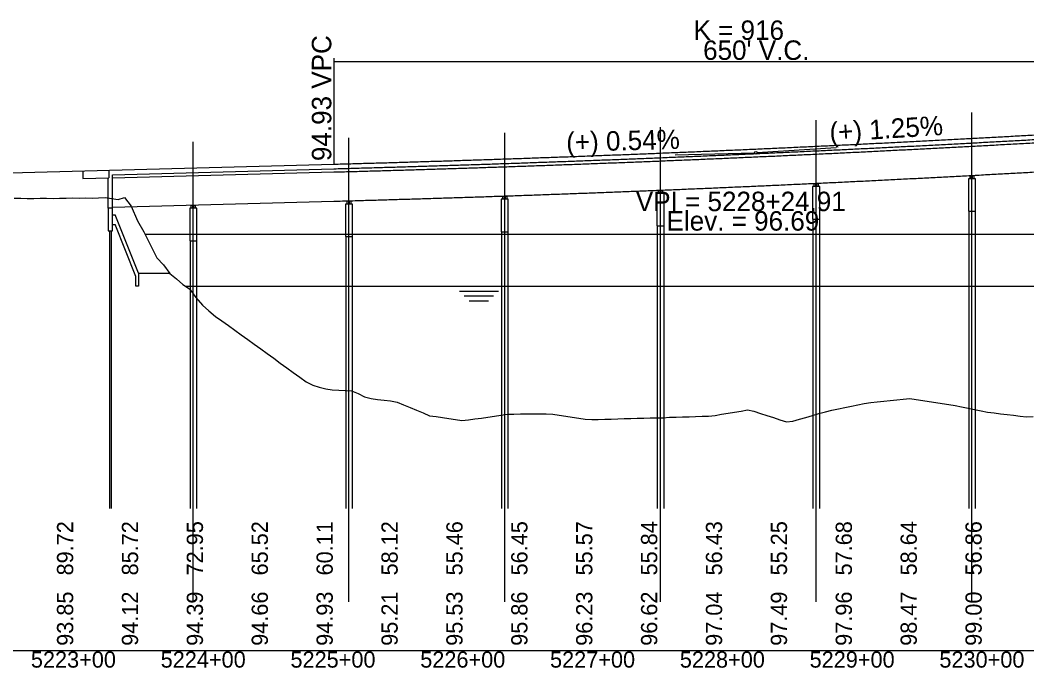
# Model space of a CAD drawing. Extents: x 2121671 to 2169879, y 557274 to 599957.
# Drawn here: x 2151826 to 2152602, y 579173 to 579672 of the extents above; entities that cross this region are included whole.
import ezdxf

# ---------------------------------------------------------------- set-up
doc = ezdxf.new("R2010")
doc.units = 0
for name, color, linetype in [('BR_CENTER LINES', 7, 'Continuous'), ('BR_CONCRETE', 7, 'Continuous'), ('BR_DETAILS', 7, 'Continuous'), ('BR_PRESTRESSED BEAM', 7, 'Continuous'), ('BR_STRUCTURAL STEEL', 7, 'Continuous'), ('RD_DDB_GradeTX', 7, 'Continuous'), ('RD_DDB_Profile_Elev', 7, 'Continuous'), ('RD_DDB_Profile_EX', 7, 'Continuous'), ('RD_DDB_Profile_Lbl', 7, 'Continuous'), ('RD_DDB_Profile_PR', 7, 'Continuous'), ('RD_DDB_StaTX', 7, 'Continuous'), ('RD_DDB_StripGrade', 7, 'Continuous'), ('RD_DDB_VCLbl', 7, 'Continuous'), ('RD_GPK_Profile_Cell', 7, 'Continuous')]:
    doc.layers.add(name, color=color, linetype=linetype)

msp = doc.modelspace()

# ---------------------------------------------------------------- linework, layer by layer
at = {"layer": 'BR_CENTER LINES'}
for p, q in [((2152559.43, 579224.3), (2152559.43, 579601.35)), ((2152439.43, 579224.3), (2152439.43, 579595.28)), ((2152319.43, 579224.3), (2152319.43, 579590)), ((2151959.43, 579224.3), (2151959.43, 579578.55)), ((2152079.43, 579224.3), (2152079.43, 579581.8)), ((2152199.43, 579224.3), (2152199.43, 579585.51))]:
    msp.add_line(p, q, dxfattribs=at)
at = {"layer": 'BR_CONCRETE'}
for p, q in [((2151874.43, 579556.26), (2151874.43, 579550.43)), ((2151894.43, 579556.8), (2151894.43, 579550.97)), ((2151897.27, 579553.33), (2152067.84, 579557.94)), ((2151874.43, 579550.43), (2151894.43, 579550.97)), ((2151893.77, 579527.54), (2151893.77, 579550.95)), ((2151897.27, 579527.54), (2151897.27, 579553.33)), ((2152556.93, 579525.23), (2152556.93, 579296.09)), ((2152561.93, 579525.23), (2152561.93, 579296.09)), ((2152436.93, 579519.17), (2152436.93, 579296.09)), ((2152441.93, 579519.17), (2152441.93, 579296.09)), ((2152196.93, 579509.41), (2152196.93, 579296.09)), ((2152201.93, 579509.41), (2152201.93, 579296.09)), ((2152316.93, 579513.9), (2152316.93, 579296.09)), ((2152321.93, 579513.9), (2152321.93, 579296.09)), ((2151956.93, 579502.47), (2151956.93, 579296.09)), ((2151961.93, 579502.47), (2151961.93, 579296.09)), ((2152076.93, 579505.71), (2152076.93, 579296.09)), ((2152081.93, 579505.71), (2152081.93, 579296.09))]:
    msp.add_line(p, q, dxfattribs=at)
for points in [[(2152556.68, 579525.23), (2152562.18, 579525.23), (2152562.18, 579550.23), (2152556.68, 579550.23)], [(2152436.68, 579519.17), (2152442.18, 579519.17), (2152442.18, 579544.17), (2152436.68, 579544.17)], [(2152196.68, 579509.41), (2152202.18, 579509.41), (2152202.18, 579534.41), (2152196.68, 579534.41)], [(2152316.68, 579513.9), (2152322.18, 579513.9), (2152322.18, 579538.9), (2152316.68, 579538.9)], [(2151893.77, 579510.04), (2151897.27, 579510.04), (2151897.27, 579527.54), (2151893.77, 579527.54)], [(2151956.68, 579502.47), (2151962.18, 579502.47), (2151962.18, 579527.47), (2151956.68, 579527.47)], [(2152076.68, 579505.71), (2152082.18, 579505.71), (2152082.18, 579530.71), (2152076.68, 579530.71)]]:
    msp.add_lwpolyline(points, close=True, dxfattribs=at)
msp.add_spline([(2152067.84, 579557.94), (2152080.84, 579558.29), (2152093.84, 579558.66), (2152106.84, 579559.03), (2152119.84, 579559.42), (2152132.84, 579559.81), (2152145.84, 579560.21), (2152158.84, 579560.62), (2152171.84, 579561.04), (2152184.84, 579561.47), (2152197.84, 579561.91), (2152210.84, 579562.36), (2152223.84, 579562.82), (2152236.84, 579563.28), (2152249.84, 579563.76), (2152262.84, 579564.24), (2152275.84, 579564.74), (2152288.84, 579565.24), (2152301.84, 579565.75), (2152314.84, 579566.27), (2152327.84, 579566.8), (2152340.84, 579567.34), (2152353.84, 579567.89), (2152366.84, 579568.45), (2152379.84, 579569.02), (2152392.84, 579569.6), (2152405.84, 579570.18), (2152418.84, 579570.78), (2152431.84, 579571.38), (2152444.84, 579572), (2152457.84, 579572.62), (2152470.84, 579573.25), (2152483.84, 579573.89), (2152496.84, 579574.55), (2152509.84, 579575.21), (2152522.84, 579575.87), (2152535.84, 579576.55), (2152548.84, 579577.24), (2152561.84, 579577.94), (2152574.84, 579578.64), (2152587.84, 579579.36), (2152600.84, 579580.08), (2152613.84, 579580.82), (2152626.84, 579581.56), (2152639.84, 579582.31), (2152652.84, 579583.08), (2152665.84, 579583.85), (2152678.84, 579584.63), (2152691.84, 579585.42), (2152704.84, 579586.21), (2152717.84, 579587.02)], degree=3, dxfattribs=at)
at = {"layer": 'BR_DETAILS'}
for p, q in [((2151897.27, 579522.54), (2151899.27, 579522.54)), ((2151917.31, 579477.43), (2151899.27, 579522.54)), ((2151897.27, 579515.04), (2151899.27, 579515.04)), ((2151915.31, 579474.93), (2151899.27, 579515.04)), ((2151917.31, 579477.43), (2151941.42, 579477.43)), ((2151917.31, 579477.43), (2151917.31, 579467.43)), ((2151915.31, 579467.43), (2151915.31, 579474.93)), ((2151917.31, 579467.43), (2151915.31, 579467.43))]:
    msp.add_line(p, q, dxfattribs=at)
for points in [[(2152557.93, 579552.73), (2152558.93, 579552.73), (2152558.93, 579550.23), (2152557.93, 579550.23)], [(2152559.93, 579552.73), (2152560.93, 579552.73), (2152560.93, 579550.23), (2152559.93, 579550.23)], [(2152317.93, 579541.4), (2152318.93, 579541.4), (2152318.93, 579538.9), (2152317.93, 579538.9)], [(2152319.93, 579541.4), (2152320.93, 579541.4), (2152320.93, 579538.9), (2152319.93, 579538.9)], [(2152437.93, 579546.67), (2152438.93, 579546.67), (2152438.93, 579544.17), (2152437.93, 579544.17)], [(2152439.93, 579546.67), (2152440.93, 579546.67), (2152440.93, 579544.17), (2152439.93, 579544.17)], [(2152077.93, 579533.21), (2152078.93, 579533.21), (2152078.93, 579530.71), (2152077.93, 579530.71)], [(2152079.93, 579533.21), (2152080.93, 579533.21), (2152080.93, 579530.71), (2152079.93, 579530.71)], [(2152197.93, 579536.91), (2152198.93, 579536.91), (2152198.93, 579534.41), (2152197.93, 579534.41)], [(2152199.93, 579536.91), (2152200.93, 579536.91), (2152200.93, 579534.41), (2152199.93, 579534.41)], [(2151957.93, 579529.97), (2151958.93, 579529.97), (2151958.93, 579527.47), (2151957.93, 579527.47)], [(2151959.93, 579529.97), (2151960.93, 579529.97), (2151960.93, 579527.47), (2151959.93, 579527.47)]]:
    msp.add_lwpolyline(points, close=True, dxfattribs=at)
at = {"layer": 'BR_PRESTRESSED BEAM'}
for p, q in [((2151897.27, 579550.83), (2152067.84, 579555.44)), ((2151897.27, 579528.33), (2152067.84, 579532.94))]:
    msp.add_line(p, q, dxfattribs=at)
for points in [[(2152067.84, 579555.44), (2152080.84, 579555.79), (2152093.84, 579556.16), (2152106.84, 579556.53), (2152119.84, 579556.92), (2152132.84, 579557.31), (2152145.84, 579557.71), (2152158.84, 579558.12), (2152171.84, 579558.54), (2152184.84, 579558.97), (2152197.84, 579559.41), (2152210.84, 579559.86), (2152223.84, 579560.32), (2152236.84, 579560.78), (2152249.84, 579561.26), (2152262.84, 579561.74), (2152275.84, 579562.24), (2152288.84, 579562.74), (2152301.84, 579563.25), (2152314.84, 579563.77), (2152327.84, 579564.3), (2152340.84, 579564.84), (2152353.84, 579565.39), (2152366.84, 579565.95), (2152379.84, 579566.52), (2152392.84, 579567.1), (2152405.84, 579567.68), (2152418.84, 579568.28), (2152431.84, 579568.88), (2152444.84, 579569.5), (2152457.84, 579570.12), (2152470.84, 579570.75), (2152483.84, 579571.39), (2152496.84, 579572.05), (2152509.84, 579572.71), (2152522.84, 579573.37), (2152535.84, 579574.05), (2152548.84, 579574.74), (2152561.84, 579575.44), (2152574.84, 579576.14), (2152587.84, 579576.86), (2152600.84, 579577.58), (2152613.84, 579578.32), (2152626.84, 579579.06), (2152639.84, 579579.81), (2152652.84, 579580.58), (2152665.84, 579581.35), (2152678.84, 579582.13), (2152691.84, 579582.92), (2152704.84, 579583.71), (2152717.84, 579584.52)], [(2152067.84, 579532.94), (2152080.84, 579533.29), (2152093.84, 579533.66), (2152106.84, 579534.03), (2152119.84, 579534.42), (2152132.84, 579534.81), (2152145.84, 579535.21), (2152158.84, 579535.62), (2152171.84, 579536.04), (2152184.84, 579536.47), (2152197.84, 579536.91), (2152210.84, 579537.36), (2152223.84, 579537.82), (2152236.84, 579538.28), (2152249.84, 579538.76), (2152262.84, 579539.24), (2152275.84, 579539.74), (2152288.84, 579540.24), (2152301.84, 579540.75), (2152314.84, 579541.27), (2152327.84, 579541.8), (2152340.84, 579542.34), (2152353.84, 579542.89), (2152366.84, 579543.45), (2152379.84, 579544.02), (2152392.84, 579544.6), (2152405.84, 579545.18), (2152418.84, 579545.78), (2152431.84, 579546.38), (2152444.84, 579547), (2152457.84, 579547.62), (2152470.84, 579548.25), (2152483.84, 579548.89), (2152496.84, 579549.55), (2152509.84, 579550.21), (2152522.84, 579550.87), (2152535.84, 579551.55), (2152548.84, 579552.24), (2152561.84, 579552.94), (2152574.84, 579553.64), (2152587.84, 579554.36), (2152600.84, 579555.08), (2152613.84, 579555.82), (2152626.84, 579556.56), (2152639.84, 579557.31), (2152652.84, 579558.08), (2152665.84, 579558.85), (2152678.84, 579559.63), (2152691.84, 579560.42), (2152704.84, 579561.21), (2152717.84, 579562.02)]]:
    msp.add_spline(points, degree=3, dxfattribs=at)
at = {"layer": 'BR_STRUCTURAL STEEL'}
for p, q in [((2151894.93, 579510.04), (2151894.93, 579296.09)), ((2151896.1, 579510.04), (2151896.1, 579296.09))]:
    msp.add_line(p, q, dxfattribs=at)
at = {"layer": 'RD_DDB_GradeTX'}
for p, q in [((2152330.87, 579568.58), (2152391.84, 579570.23)), ((2152454.72, 579574.12), (2152393.84, 579570.32))]:
    msp.add_line(p, q, dxfattribs=at)
msp.add_circle((2152392.84, 579570.26), 1, dxfattribs=at)
at = {"layer": 'RD_DDB_Profile_Elev'}
for p, q in [((2151922.43, 579507.43), (2155499.43, 579507.43)), ((2151953.51, 579467.43), (2156316.65, 579467.43)), ((2152164.52, 579463.68), (2152194.52, 579463.68)), ((2152168.27, 579459.93), (2152190.77, 579459.93)), ((2152172.02, 579456.18), (2152187.02, 579456.18))]:
    msp.add_line(p, q, dxfattribs=at)
at = {"layer": 'RD_DDB_Profile_EX'}
for points in [[(2151821.48, 579535.34), (2151826.48, 579535.31), (2151831.48, 579534.89), (2151836.48, 579535.06), (2151841.48, 579535.2), (2151846.48, 579535.14), (2151851.48, 579535.04), (2151856.48, 579535.15), (2151861.48, 579535.34), (2151866.48, 579535.5), (2151871.48, 579535.33), (2151876.48, 579535.43), (2151881.48, 579535.37), (2151886.48, 579535.61), (2151891.48, 579535.87), (2151896.48, 579535.04), (2151901.48, 579534.3), (2151906.48, 579535.89), (2151911.48, 579528.98), (2151916.48, 579517.87), (2151921.48, 579509.4), (2151926.48, 579499.02), (2151931.48, 579489.36), (2151936.48, 579483.82), (2151941.48, 579477.34), (2151946.48, 579473.09), (2151951.48, 579468.83), (2151956.48, 579465.38), (2151961.48, 579458.79), (2151966.48, 579452.85), (2151971.48, 579448.44), (2151976.48, 579444.15), (2151981.48, 579440.71), (2151986.48, 579437.18), (2151991.48, 579433.56), (2151996.48, 579429.95), (2152001.48, 579426.33), (2152006.48, 579422.71), (2152011.48, 579419.1), (2152016.48, 579415.48), (2152021.48, 579411.86), (2152026.48, 579408.25), (2152031.48, 579404.63), (2152036.48, 579401.01), (2152041.48, 579397.4), (2152046.48, 579393.78), (2152051.48, 579391.16), (2152056.48, 579389.75), (2152061.48, 579388.33), (2152066.48, 579387.46), (2152071.48, 579387.24), (2152076.48, 579387.01), (2152081.48, 579386.79), (2152086.48, 579384.74), (2152091.48, 579382.28), (2152096.48, 579380.78), (2152101.48, 579380.19), (2152106.48, 579379.61), (2152111.48, 579379.02), (2152116.48, 579377.99), (2152121.48, 579375.97), (2152126.48, 579373.96), (2152131.48, 579371.94), (2152136.48, 579369.92), (2152141.48, 579367.66), (2152146.48, 579366.93), (2152151.48, 579366.2), (2152156.48, 579365.47), (2152161.48, 579364.75), (2152166.48, 579364.02), (2152171.48, 579364.36), (2152176.48, 579365.12), (2152181.48, 579365.85), (2152186.48, 579366.58), (2152191.48, 579367.31), (2152196.48, 579368.03), (2152201.48, 579368.74), (2152206.48, 579368.91), (2152211.48, 579368.98), (2152216.48, 579369.05), (2152221.48, 579369.13)], [(2152221.48, 579369.13), (2152226.48, 579369.2), (2152231.48, 579369.17), (2152236.48, 579368.84), (2152241.48, 579368.06), (2152246.48, 579367.27), (2152251.48, 579366.49), (2152256.48, 579365.71), (2152261.48, 579364.92), (2152266.48, 579364.62), (2152271.48, 579364.77), (2152276.48, 579364.93), (2152281.48, 579365.08), (2152286.48, 579365.23), (2152291.48, 579365.38), (2152296.48, 579365.61), (2152301.48, 579365.71), (2152306.48, 579365.81), (2152311.48, 579365.91), (2152316.48, 579366.02), (2152321.48, 579366.12), (2152326.48, 579366.49), (2152331.48, 579366.63), (2152336.48, 579366.77), (2152341.48, 579366.9), (2152346.48, 579367.04), (2152351.48, 579367.18), (2152356.48, 579367.19), (2152361.48, 579367.91), (2152366.48, 579368.74), (2152371.48, 579369.57), (2152376.48, 579370.4), (2152381.48, 579371.23), (2152386.48, 579372.06), (2152391.48, 579371.02), (2152396.48, 579369.41), (2152401.48, 579367.79), (2152406.48, 579366.18), (2152411.48, 579364.56), (2152416.48, 579362.95), (2152421.48, 579363.4), (2152426.48, 579364.86), (2152431.48, 579366.33), (2152436.48, 579367.79), (2152441.48, 579369.26), (2152446.48, 579370.72), (2152451.48, 579371.86), (2152456.48, 579372.89), (2152461.48, 579373.92), (2152466.48, 579374.95), (2152471.48, 579375.97), (2152476.48, 579377), (2152481.48, 579377.88), (2152486.48, 579378.4), (2152491.48, 579378.93), (2152496.48, 579379.45), (2152501.48, 579379.97), (2152506.48, 579380.49), (2152511.48, 579381.02), (2152516.48, 579380.26), (2152521.48, 579379.48), (2152526.48, 579378.7), (2152531.48, 579377.91), (2152536.48, 579377.13), (2152541.48, 579376.34), (2152546.48, 579375.4), (2152551.48, 579374.4), (2152556.48, 579373.41), (2152561.48, 579372.42), (2152566.48, 579371.43), (2152571.48, 579370.44), (2152576.48, 579369.76), (2152581.48, 579369.16), (2152586.48, 579368.56), (2152591.48, 579367.97), (2152596.48, 579367.37), (2152601.48, 579366.77), (2152606.48, 579366.92)]]:
    msp.add_lwpolyline(points, dxfattribs=at)
at = {"layer": 'RD_DDB_Profile_PR'}
msp.add_line((2151221.48, 579538.63), (2152067.84, 579561.48), dxfattribs=at)
msp.add_spline([(2152067.84, 579561.48), (2152080.84, 579561.84), (2152093.84, 579562.2), (2152106.84, 579562.57), (2152119.84, 579562.96), (2152132.84, 579563.35), (2152145.84, 579563.75), (2152158.84, 579564.16), (2152171.84, 579564.58), (2152184.84, 579565.01), (2152197.84, 579565.45), (2152210.84, 579565.9), (2152223.84, 579566.36), (2152236.84, 579566.82), (2152249.84, 579567.3), (2152262.84, 579567.78), (2152275.84, 579568.28), (2152288.84, 579568.78), (2152301.84, 579569.29), (2152314.84, 579569.81), (2152327.84, 579570.35), (2152340.84, 579570.89), (2152353.84, 579571.44), (2152366.84, 579571.99), (2152379.84, 579572.56), (2152392.84, 579573.14), (2152405.84, 579573.72), (2152418.84, 579574.32), (2152431.84, 579574.93), (2152444.84, 579575.54), (2152457.84, 579576.16), (2152470.84, 579576.79), (2152483.84, 579577.44), (2152496.84, 579578.09), (2152509.84, 579578.75), (2152522.84, 579579.42), (2152535.84, 579580.1), (2152548.84, 579580.78), (2152561.84, 579581.48), (2152574.84, 579582.19), (2152587.84, 579582.9), (2152600.84, 579583.63), (2152613.84, 579584.36), (2152626.84, 579585.1), (2152639.84, 579585.86), (2152652.84, 579586.62), (2152665.84, 579587.39), (2152678.84, 579588.17), (2152691.84, 579588.96), (2152704.84, 579589.76), (2152717.84, 579590.56)], degree=3, dxfattribs=at)
at = {"layer": 'RD_DDB_VCLbl'}
for p, q in [((2152067.84, 579643.06), (2152067.84, 579561.48)), ((2152067.84, 579640.56), (2152717.84, 579640.56))]:
    msp.add_line(p, q, dxfattribs=at)
at = {"layer": 'RD_GPK_Profile_Cell'}
msp.add_line((2151067.93, 579186.83), (2157367.93, 579186.83), dxfattribs=at)

# ---------------------------------------------------------------- texts
at = {"layer": 'RD_DDB_GradeTX'}
for s, rotation, p in [('(+) 1.25%', 3.57557, (2152450.12, 579578.49)), ('(+) 0.54%', 1.54661, (2152247, 579570.92))]:
    msp.add_text(s, height=15, rotation=rotation, dxfattribs=at).set_placement(p)
at = {"layer": 'RD_DDB_Profile_Lbl'}
for s, p in [('VPI = 5228+24.91', (2152300.48, 579525.26)), ('Elev. = 96.69', (2152324.12, 579510.26))]:
    msp.add_text(s, height=15, dxfattribs=at).set_placement(p)
at = {"layer": 'RD_DDB_StaTX'}
for s, p in [('5223+00', (2151834.32, 579173.53)), ('5224+00', (2151934.32, 579173.53)), ('5225+00', (2152034.32, 579173.53)), ('5226+00', (2152134.32, 579173.53)), ('5227+00', (2152234.32, 579173.53)), ('5228+00', (2152334.32, 579173.53)), ('5229+00', (2152434.32, 579173.53)), ('5230+00', (2152534.32, 579173.53))]:
    msp.add_text(s, height=12.5, dxfattribs=at).set_placement(p)
at = {"layer": 'RD_DDB_StripGrade'}
for s, height, p in [('94.93 VPC', 15, (2152065.8, 579563.84)), ('89.72', 12.5, (2151866.93, 579244.56)), ('85.72', 12.5, (2151916.93, 579244.56)), ('72.95', 12.5, (2151966.93, 579244.56)), ('65.52', 12.5, (2152016.93, 579244.56)), ('60.11', 12.5, (2152066.93, 579244.56)), ('58.12', 12.5, (2152116.93, 579244.56)), ('55.46', 12.5, (2152166.93, 579244.56)), ('56.45', 12.5, (2152216.93, 579244.56)), ('55.57', 12.5, (2152266.93, 579244.56)), ('55.84', 12.5, (2152316.93, 579244.56)), ('56.43', 12.5, (2152366.93, 579244.56)), ('55.25', 12.5, (2152416.93, 579244.56)), ('57.68', 12.5, (2152466.93, 579244.56)), ('58.64', 12.5, (2152516.93, 579244.56)), ('56.86', 12.5, (2152566.93, 579244.56)), ('93.85', 12.5, (2151866.93, 579190.33)), ('94.12', 12.5, (2151916.93, 579190.33)), ('94.39', 12.5, (2151966.93, 579190.33)), ('94.66', 12.5, (2152016.93, 579190.33)), ('94.93', 12.5, (2152066.93, 579190.33)), ('95.21', 12.5, (2152116.93, 579190.33)), ('95.53', 12.5, (2152166.93, 579190.33)), ('95.86', 12.5, (2152216.93, 579190.33)), ('96.23', 12.5, (2152266.93, 579190.33)), ('96.62', 12.5, (2152316.93, 579190.33)), ('97.04', 12.5, (2152366.93, 579190.33)), ('97.49', 12.5, (2152416.93, 579190.33)), ('97.96', 12.5, (2152466.93, 579190.33)), ('98.47', 12.5, (2152516.93, 579190.33)), ('99.00', 12.5, (2152566.93, 579190.33))]:
    msp.add_text(s, height=height, rotation=90, dxfattribs=at).set_placement(p)
at = {"layer": 'RD_DDB_VCLbl'}
for s, p in [('K = 916', (2152344.9, 579657.22)), ("650' V.C.", (2152352.29, 579641.81))]:
    msp.add_text(s, height=15, dxfattribs=at).set_placement(p)

doc.saveas('drawing.dxf')
